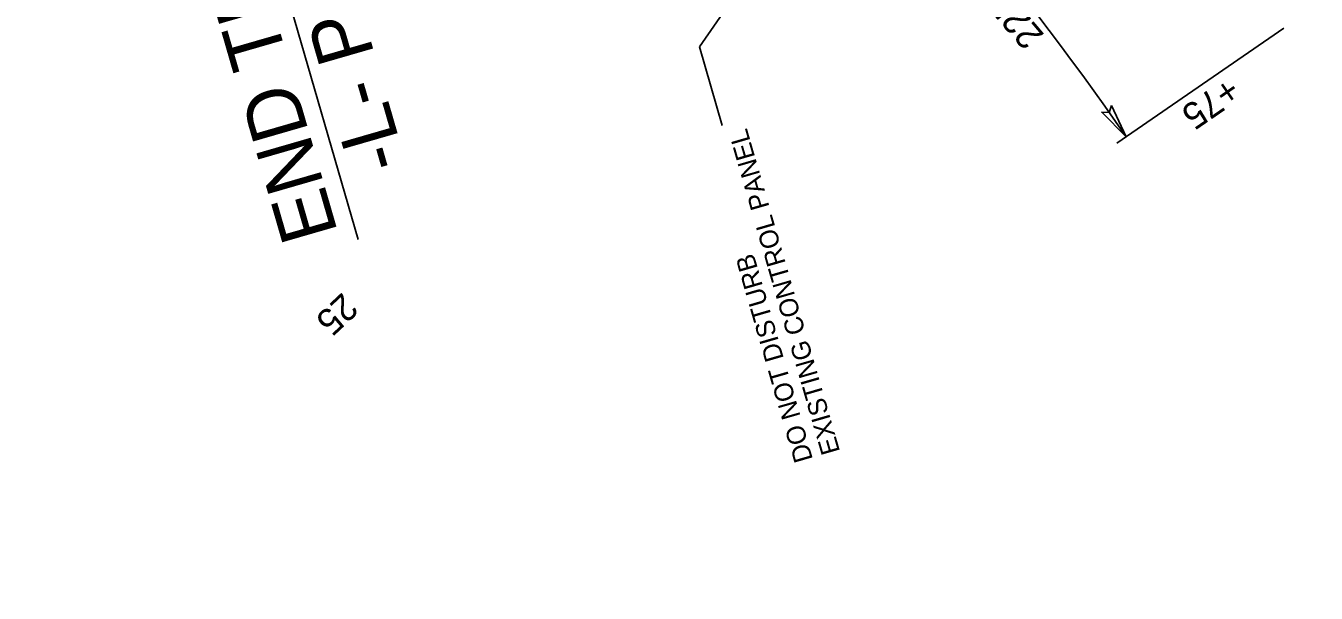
# Model space of a CAD drawing. Extents: x 2167182 to 2168576, y 842635 to 844493.
# Drawn here: x 2167512.1 to 2167855, y 843798.4 to 843949.1 of the extents above; entities that cross this region are included whole.
import ezdxf

# ---------------------------------------------------------------- set-up
doc = ezdxf.new("R2010")
doc.units = 0
for name, color, linetype in [('Old_Level_2', 7, 'Continuous'), ('Prop Dimension', 7, 'Continuous'), ('Prop Dimension Text', 7, 'Continuous'), ('Prop EOT', 7, 'Continuous'), ('Prop Horizontal Alignment', 7, 'Continuous'), ('Prop Horizontal Alignment Tick Label', 7, 'Continuous'), ('Prop Shade Light', 7, 'Continuous'), ('Prop Terminator CELL', 7, 'Continuous')]:
    doc.layers.add(name, color=color, linetype=linetype)

msp = doc.modelspace()

# ---------------------------------------------------------------- linework, layer by layer
at = {"layer": 'Prop Dimension'}
for p, q in [((2167600.36, 843892.31), (2167525.56, 844151.38)), ((2167691.08, 843943.53), (2167728.05, 843996.78)), ((2167802, 843917.93), (2167846.36, 843948.49)), ((2167691.08, 843943.53), (2167697.12, 843922.6))]:
    msp.add_line(p, q, dxfattribs=at)
msp.add_arc((2167204.29, 843506.02), 728.9, 34.57168, 47.10916, dxfattribs=at)
at = {"layer": 'Prop EOT'}
msp.add_arc((2167204.29, 843506.02), 844, 7.27898, 47.10916, dxfattribs=at)
at = {"layer": 'Prop Horizontal Alignment'}
msp.add_arc((2167204.29, 843506.02), 833, 7.27898, 47.10916, dxfattribs=at)
at = {"layer": 'Prop Shade Light'}
for radius, start in [(848, 16.19989), (844, 7.27898)]:
    msp.add_arc((2167204.29, 843506.02), radius, start, 47.10916, dxfattribs=at)
at = {"layer": 'Prop Terminator CELL'}
msp.add_lwpolyline([(2167800.59, 843927.9), (2167804.47, 843919.63), (2167797.98, 843926.13), (2167799.95, 843926.11)], close=True, dxfattribs=at)

# ---------------------------------------------------------------- texts
at = {"layer": 'Old_Level_2'}
for s, p in [('END TIP PROJECT B-5325', (2167595.08, 843894.19)), ('-L- POC STA 26+50.00', (2167613.18, 843912.59))]:
    msp.add_text(s, height=15, rotation=106.1263, dxfattribs=at).set_placement(p)
at = {"layer": 'Prop Dimension Text'}
for s, height, rotation, p in [("225' LANE TAPER LT", 7, 130.5281, (2167782.91, 843946.7)), ('+75', 7, 214.5717, (2167831.66, 843935.87)), ('EXISTING CONTROL PANEL', 5, 106.1042, (2167728.48, 843836.05)), ('DO NOT DISTURB', 5, 106.1042, (2167721.27, 843833.97))]:
    msp.add_text(s, height=height, rotation=rotation, dxfattribs=at).set_placement(p)
at = {"layer": 'Prop Horizontal Alignment Tick Label'}
msp.add_text('25', height=7, rotation=223.1695, dxfattribs=at).set_placement((2167596.25, 843878.51))

doc.saveas('drawing.dxf')
